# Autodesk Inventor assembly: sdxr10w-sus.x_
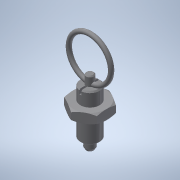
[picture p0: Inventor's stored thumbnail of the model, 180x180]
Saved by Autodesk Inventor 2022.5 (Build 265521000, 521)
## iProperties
Part Number: sdxr10w-sus.x_
Material: 一般
Document SubType Name: Assembly
Designer: ImaoCorp
Sending System: SOLIDWORKS 2017-2017317
MC: AMD64
MC_MODEL: Intel64 Family 6 Model 60 Stepping 3, GenuineIntel
OS: Windows_NT
FRU: Parasolid Version 29.0, build 201,  4-17-2017
FORMAT: text
GUISE: transmit
KEY: sdxr10w-sus
FILE: sdxr10w-sus.x_t
DATE: Wed Sep 18 16:15:47 2019
Author: ImaoCorp
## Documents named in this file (3)
- X:\14_SW2022-Inv2022\00_全2023-1023新製品(TCC)まで\s\sdxr10w-sus\SDXR10W-SUS.iam
- X:\14_SW2022-Inv2022\00_全2023-1023新製品(TCC)まで\s\sdxr10w-sus\sdxr10w-sus_01.ipt
- X:\14_SW2022-Inv2022\00_全2023-1023新製品(TCC)まで\s\sdxr10w-sus\sdxr10w-sus_02.ipt
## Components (2 placed, 2 different names)
1. sdxr10w-sus_01
2. sdxr10w-sus_02
